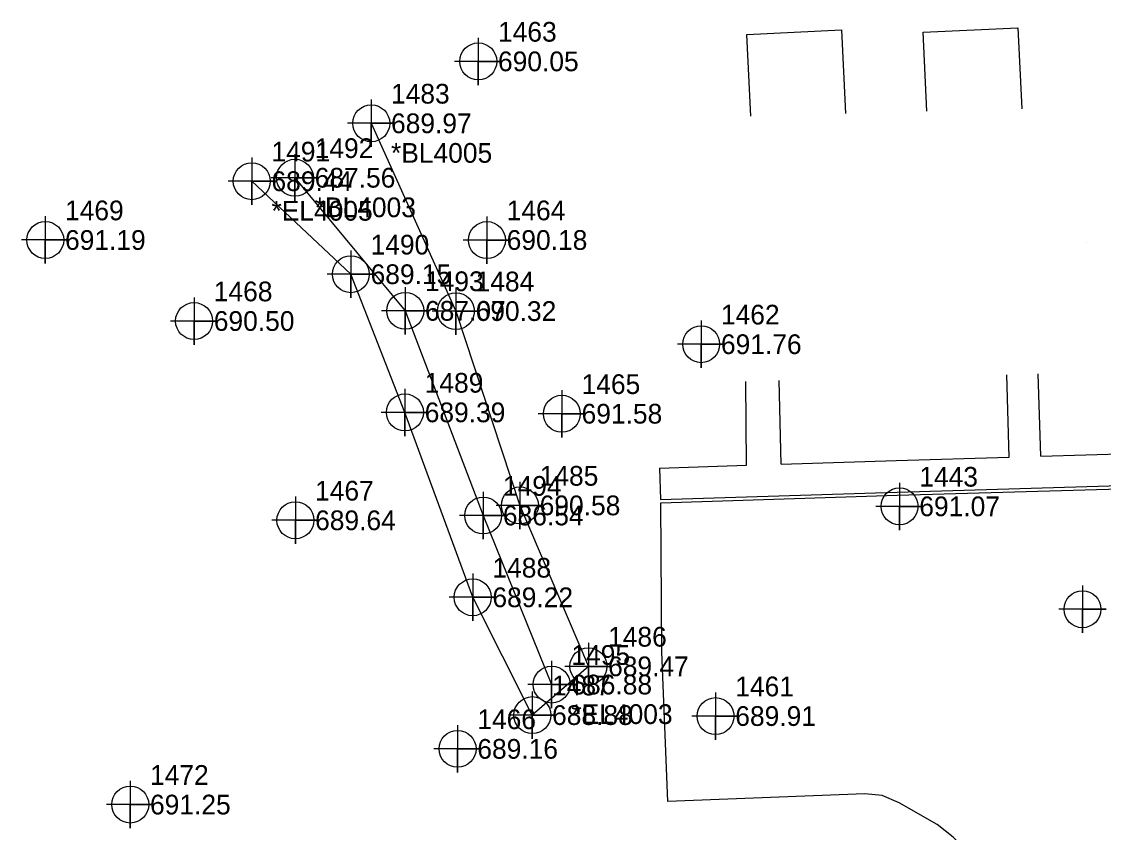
# Model space of a CAD drawing. Extents: x 1755643 to 1760494, y 736519 to 737621.
# Drawn here: x 1757880.4 to 1758017.5, y 737040.2 to 737142.9 of the extents above; entities that cross this region are included whole.
import ezdxf

# ---------------------------------------------------------------- set-up
doc = ezdxf.new("R2010")
doc.units = 0
for name, color, linetype in [('Exist Horizontal Alignment Curve and Spiral Data', 7, 'Continuous'), ('Exist Horizontal Alignment Direction Label', 7, 'Continuous'), ('Exist Railroads Standard Gauge', 7, 'Continuous'), ('Exist Roads EOT', 7, 'Continuous'), ('Old_Level_1', 7, 'Continuous'), ('Old_Level_10', 7, 'Continuous'), ('Old_Level_2', 7, 'Continuous'), ('Old_Level_3', 7, 'Continuous'), ('Prop Dimension', 7, 'Continuous'), ('Prop EOT Dash', 7, 'Continuous'), ('Prop Horizontal Alignment Direction Label', 7, 'Continuous'), ('Prop Lane Lines', 7, 'Continuous'), ('Prop Paint Stripe', 7, 'Continuous'), ('Prop Paved Shoulder', 7, 'Continuous'), ('Scratch_Level_9', 7, 'Continuous')]:
    doc.layers.add(name, color=color, linetype=linetype)

msp = doc.modelspace()

# ---------------------------------------------------------------- linework, layer by layer
at = {"layer": 'Exist Horizontal Alignment Curve and Spiral Data'}
for points in [[(1757938.27, 737140.91), (1757938.27, 737134.91), (1757938.27, 737137.91), (1757941.27, 737137.91), (1757935.27, 737137.91)], [(1757883.4, 737118.27), (1757883.4, 737112.27), (1757883.4, 737115.27), (1757886.4, 737115.27), (1757880.4, 737115.27)], [(1757939.37, 737118.26), (1757939.37, 737112.26), (1757939.37, 737115.26), (1757942.37, 737115.26), (1757936.37, 737115.26)], [(1757902.25, 737108), (1757902.25, 737102), (1757902.25, 737105), (1757905.25, 737105), (1757899.25, 737105)], [(1757966.52, 737105.06), (1757966.52, 737099.06), (1757966.52, 737102.06), (1757969.52, 737102.06), (1757963.52, 737102.06)], [(1757948.86, 737096.25), (1757948.86, 737090.25), (1757948.86, 737093.25), (1757951.86, 737093.25), (1757945.86, 737093.25)], [(1757991.66, 737084.51), (1757991.66, 737078.51), (1757991.66, 737081.51), (1757994.66, 737081.51), (1757988.66, 737081.51)], [(1757915.09, 737082.74), (1757915.09, 737076.74), (1757915.09, 737079.74), (1757918.09, 737079.74), (1757912.09, 737079.74)], [(1758014.84, 737071.46), (1758014.84, 737065.46), (1758014.84, 737068.46), (1758017.84, 737068.46), (1758011.84, 737068.46)], [(1757968.34, 737057.92), (1757968.34, 737051.92), (1757968.34, 737054.92), (1757971.34, 737054.92), (1757965.34, 737054.92)], [(1757935.65, 737053.77), (1757935.65, 737047.77), (1757935.65, 737050.77), (1757938.65, 737050.77), (1757932.65, 737050.77)], [(1757894.17, 737046.71), (1757894.17, 737040.71), (1757894.17, 737043.71), (1757897.17, 737043.71), (1757891.17, 737043.71)]]:
    msp.add_lwpolyline(points, dxfattribs=at)
for centre in [(1757938.27, 737137.91), (1757883.4, 737115.27), (1757939.37, 737115.26), (1757902.25, 737105), (1757966.52, 737102.06), (1757948.86, 737093.25), (1757991.66, 737081.51), (1757915.09, 737079.74), (1758014.84, 737068.46), (1757968.34, 737054.92), (1757935.65, 737050.77), (1757894.17, 737043.71)]:
    msp.add_circle(centre, 2.34, dxfattribs=at)
at = {"layer": 'Exist Railroads Standard Gauge'}
for p, q in [((1757972.25, 737086.71), (1757972.18, 737097.34)), ((1757976.64, 737086.85), (1757976.41, 737097.46)), ((1758005.54, 737087.74), (1758005.25, 737098.19)), ((1758009.58, 737087.86), (1758009.23, 737098.3)), ((1757961.25, 737086.36), (1757961.38, 737082.36)), ((1757961.55, 737063.08), (1757961.39, 737081.94))]:
    msp.add_line(p, q, dxfattribs=at)
for points in [[(1757995.12, 737131.58), (1757994.64, 737141.6), (1758006.64, 737142.18), (1758007.14, 737131.9)], [(1757972.79, 737130.98), (1757972.29, 737141.32), (1757984.29, 737141.9), (1757984.81, 737131.3)], [(1757976.64, 737086.85), (1757991.23, 737087.32), (1758005.54, 737087.74)], [(1758009.58, 737087.86), (1758020.95, 737088.2)], [(1757961.25, 737086.36), (1757972.25, 737086.71)], [(1757961.38, 737082.36), (1757991.35, 737083.32), (1758021.07, 737084.2)], [(1757961.39, 737081.94), (1757991.37, 737082.91), (1758021.08, 737083.78)], [(1758006.04, 737029.34), (1758004.66, 737031.64), (1758003.4, 737033.81), (1758001.69, 737035.95), (1758000.17, 737037.86), (1757998.47, 737039.56), (1757996.41, 737041.2), (1757991.6, 737043.92), (1757989.45, 737044.86), (1757987.27, 737045.06), (1757962.3, 737044.11), (1757961.55, 737063.08)]]:
    msp.add_lwpolyline(points, dxfattribs=at)
at = {"layer": 'Old_Level_10'}
for points in [[(1757915.04, 737126.16), (1757915.04, 737120.16), (1757915.04, 737123.16), (1757918.04, 737123.16), (1757912.04, 737123.16)], [(1757929.02, 737109.29), (1757929.02, 737103.29), (1757929.02, 737106.29), (1757932.02, 737106.29), (1757926.02, 737106.29)], [(1757938.89, 737083.35), (1757938.89, 737077.35), (1757938.89, 737080.35), (1757941.89, 737080.35), (1757935.89, 737080.35)], [(1757947.57, 737061.92), (1757947.57, 737055.92), (1757947.57, 737058.92), (1757950.57, 737058.92), (1757944.57, 737058.92)]]:
    msp.add_lwpolyline(points, dxfattribs=at)
for centre in [(1757915.04, 737123.16), (1757929.02, 737106.29), (1757938.89, 737080.35), (1757947.57, 737058.92)]:
    msp.add_circle(centre, 2.34, dxfattribs=at)
at = {"layer": 'Prop Dimension'}
msp.add_lwpolyline([(1757915.04, 737123.16), (1757929.02, 737106.29), (1757938.89, 737080.35), (1757947.57, 737058.92)], dxfattribs=at)
at = {"layer": 'Prop Lane Lines'}
for points in [[(1757924.71, 737133.06), (1757924.71, 737127.06), (1757924.71, 737130.06), (1757927.71, 737130.06), (1757921.71, 737130.06)], [(1757909.56, 737125.72), (1757909.56, 737119.72), (1757909.56, 737122.72), (1757912.56, 737122.72), (1757906.56, 737122.72)], [(1757922.12, 737113.93), (1757922.12, 737107.93), (1757922.12, 737110.93), (1757925.12, 737110.93), (1757919.12, 737110.93)], [(1757935.43, 737109.25), (1757935.43, 737103.25), (1757935.43, 737106.25), (1757938.43, 737106.25), (1757932.43, 737106.25)], [(1757928.98, 737096.42), (1757928.98, 737090.42), (1757928.98, 737093.42), (1757931.98, 737093.42), (1757925.98, 737093.42)], [(1757943.55, 737084.63), (1757943.55, 737078.63), (1757943.55, 737081.63), (1757946.55, 737081.63), (1757940.55, 737081.63)], [(1757937.56, 737072.98), (1757937.56, 737066.98), (1757937.56, 737069.98), (1757940.56, 737069.98), (1757934.56, 737069.98)], [(1757952.22, 737064.23), (1757952.22, 737058.23), (1757952.22, 737061.23), (1757955.22, 737061.23), (1757949.22, 737061.23)], [(1757945.12, 737058.05), (1757945.12, 737052.05), (1757945.12, 737055.05), (1757948.12, 737055.05), (1757942.12, 737055.05)]]:
    msp.add_lwpolyline(points, dxfattribs=at)
for centre in [(1757924.71, 737130.06), (1757909.56, 737122.72), (1757922.12, 737110.93), (1757935.43, 737106.25), (1757928.98, 737093.42), (1757943.55, 737081.63), (1757937.56, 737069.98), (1757952.22, 737061.23), (1757945.12, 737055.05)]:
    msp.add_circle(centre, 2.34, dxfattribs=at)
at = {"layer": 'Prop Paint Stripe'}
msp.add_line((1758015.4, 737115), (1758015.4, 737115), dxfattribs=at)
at = {"layer": 'Scratch_Level_9'}
msp.add_lwpolyline([(1757924.71, 737130.06), (1757935.43, 737106.25), (1757943.55, 737081.63), (1757952.22, 737061.23), (1757945.12, 737055.05), (1757937.56, 737069.98), (1757928.98, 737093.42), (1757922.12, 737110.93), (1757909.56, 737122.72)], dxfattribs=at)

# ---------------------------------------------------------------- texts
at = {"layer": 'Exist Horizontal Alignment Direction Label'}
for s, p in [('*BL4005', (1757927.21, 737125.06)), ('*EL4005', (1757912.06, 737117.72))]:
    msp.add_text(s, height=2.5, dxfattribs=at).set_placement(p)
at = {"layer": 'Exist Roads EOT'}
for s, p in [('1463', (1757940.77, 737140.41)), ('1469', (1757885.9, 737117.77)), ('1464', (1757941.87, 737117.77)), ('1468', (1757904.75, 737107.5)), ('1462', (1757969.02, 737104.56)), ('1465', (1757951.36, 737095.75)), ('1443', (1757994.16, 737084.01)), ('1467', (1757917.59, 737082.24)), ('1461', (1757970.84, 737057.43)), ('1466', (1757938.15, 737053.27)), ('1472', (1757896.67, 737046.21))]:
    msp.add_text(s, height=2.5, dxfattribs=at).set_placement(p)
at = {"layer": 'Old_Level_1'}
for s, p in [('1492', (1757917.54, 737125.66)), ('1493', (1757931.52, 737108.79)), ('1494', (1757941.39, 737082.85)), ('1495', (1757950.07, 737061.42))]:
    msp.add_text(s, height=2.5, dxfattribs=at).set_placement(p)
at = {"layer": 'Old_Level_2'}
for s, p in [('687.56', (1757917.54, 737121.91)), ('687.07', (1757931.52, 737105.04)), ('686.54', (1757941.39, 737079.1)), ('686.88', (1757950.07, 737057.67))]:
    msp.add_text(s, height=2.5, dxfattribs=at).set_placement(p)
at = {"layer": 'Old_Level_3'}
for s, p in [('689.97', (1757927.21, 737128.81)), ('689.44', (1757912.06, 737121.47)), ('689.15', (1757924.62, 737109.68)), ('690.32', (1757937.93, 737105.01)), ('689.39', (1757931.48, 737092.17)), ('690.58', (1757946.05, 737080.38)), ('689.22', (1757940.06, 737068.73)), ('689.47', (1757954.72, 737059.98)), ('688.88', (1757947.62, 737053.8))]:
    msp.add_text(s, height=2.5, dxfattribs=at).set_placement(p)
at = {"layer": 'Prop EOT Dash'}
for s, p in [('1483', (1757927.21, 737132.56)), ('1491', (1757912.06, 737125.22)), ('1490', (1757924.62, 737113.43)), ('1484', (1757937.93, 737108.76)), ('1489', (1757931.48, 737095.92)), ('1485', (1757946.05, 737084.13)), ('1488', (1757940.06, 737072.48)), ('1486', (1757954.72, 737063.73)), ('1487', (1757947.62, 737057.55))]:
    msp.add_text(s, height=2.5, dxfattribs=at).set_placement(p)
at = {"layer": 'Prop Horizontal Alignment Direction Label'}
for s, p in [('*BL4003', (1757917.54, 737118.16)), ('*EL4003', (1757950.07, 737053.92))]:
    msp.add_text(s, height=2.5, dxfattribs=at).set_placement(p)
at = {"layer": 'Prop Paved Shoulder'}
for s, p in [('690.05', (1757940.77, 737136.66)), ('691.19', (1757885.9, 737114.02)), ('690.18', (1757941.87, 737114.02)), ('690.50', (1757904.75, 737103.75)), ('691.76', (1757969.02, 737100.81)), ('691.58', (1757951.36, 737092)), ('691.07', (1757994.16, 737080.26)), ('689.64', (1757917.59, 737078.49)), ('689.91', (1757970.84, 737053.68)), ('689.16', (1757938.15, 737049.52)), ('691.25', (1757896.67, 737042.46))]:
    msp.add_text(s, height=2.5, dxfattribs=at).set_placement(p)

doc.saveas('drawing.dxf')
